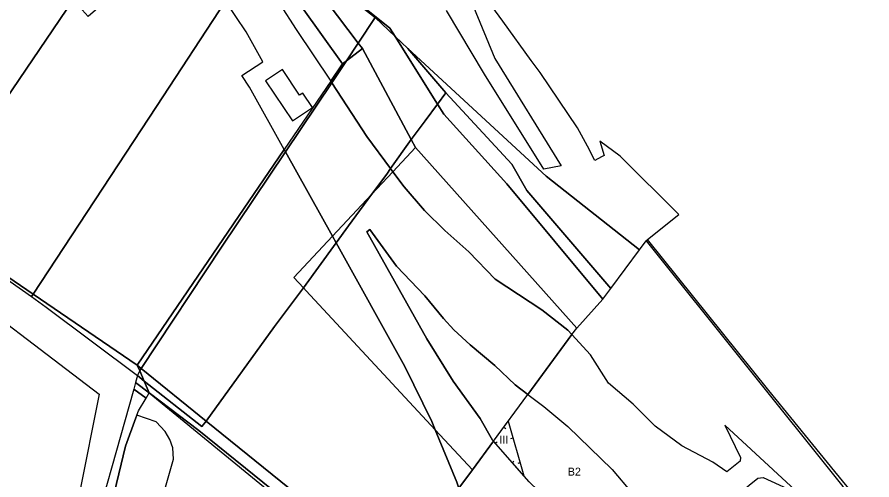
# Model space of a CAD drawing. Extents: x -749314 to -746497, y -1026537 to -1024935.
# Drawn here: x -747475.9 to -747208.9, y -1025525.6 to -1025381 of the extents above; entities that cross this region are included whole.
import ezdxf

# ---------------------------------------------------------------- set-up
doc = ezdxf.new("R2010")
doc.units = 0
for name, color, linetype in [('Default', 7, 'Continuous'), ('K_CD1', 7, 'Continuous'), ('K_JVL', 7, 'Continuous'), ('K_SZDC1', 7, 'Continuous'), ('K_VBP', 7, 'Continuous')]:
    doc.layers.add(name, color=color, linetype=linetype)

msp = doc.modelspace()

# ---------------------------------------------------------------- linework, layer by layer
for points in [[(-747323.86, -1025509.05), (-747323.25, -1025509.5)], [(-747326.54, -1025514.15), (-747325.97, -1025513.66)], [(-747321.03, -1025512.55), (-747321.75, -1025512.75)], [(-747321.28, -1025520.18), (-747320.71, -1025519.68)], [(-747318.83, -1025520.24), (-747319.55, -1025520.45)]]:
    msp.add_lwpolyline(points)
at = {"layer": 'Default'}
for points in [[(-747392.07, -1025423.06), (-747412.02, -1025452.86), (-747437.12, -1025490.76), (-747416.82, -1025507.19), (-747395.49, -1025477.61), (-747386.44, -1025465.56), (-747389.47, -1025462.29), (-747377.41, -1025449.42)], [(-747506.57, -1025443.57), (-747471.41, -1025468.26), (-747470.93, -1025467.52), (-747500.33, -1025447.44), (-747506.13, -1025442.99)], [(-747437.61, -1025491.48), (-747436.18, -1025494.75), (-747418.18, -1025508.87), (-747416.82, -1025507.19), (-747437.12, -1025490.76)]]:
    msp.add_lwpolyline(points, close=True, dxfattribs=at)
msp.add_lwpolyline([(-747316, -1025526.23), (-747327.12, -1025513.48), (-747333.7, -1025522.43), (-747337.88, -1025528.12)], dxfattribs=at)
at = {"layer": 'K_CD1'}
for points in [[(-747352.77, -1025419.24), (-747368.06, -1025390.77), (-747373.01, -1025394.6), (-747377.63, -1025401.49), (-747366.72, -1025418.25), (-747359.26, -1025428.31)], [(-747359.26, -1025428.31), (-747366.72, -1025418.25), (-747377.63, -1025401.49), (-747392.07, -1025423.06), (-747377.41, -1025449.42), (-747365.16, -1025436.35), (-747360.47, -1025430)], [(-747208.9, -1025537.01), (-747220.47, -1025522.93), (-747241.05, -1025497.59), (-747278.95, -1025450.46), (-747279.42, -1025450.84), (-747217.97, -1025527.65)], [(-747438.3, -1025492.99), (-747436.18, -1025494.75), (-747437.61, -1025491.48)], [(-747438.92, -1025495.12), (-747439.45, -1025497.23), (-747435.59, -1025500.01), (-747434.61, -1025498.37)], [(-747361.12, -1025558.08), (-747384.53, -1025538.06), (-747419.14, -1025510.09), (-747434.61, -1025498.37), (-747361.5, -1025558.41)], [(-747284.04, -1025556.36), (-747293.03, -1025547.63), (-747304.14, -1025537.68), (-747316, -1025526.23), (-747327.12, -1025513.48), (-747316.37, -1025498.86), (-747311.37, -1025502.69), (-747303.85, -1025508.85), (-747290.08, -1025522.29), (-747283.88, -1025529.61), (-747275.54, -1025541.17), (-747275.35, -1025542.26), (-747276.77, -1025544.52), (-747277.61, -1025546.19), (-747278.64, -1025548.98), (-747279.07, -1025550.95), (-747279.9, -1025553.1), (-747281.55, -1025559.79)], [(-747442.08, -1025515.07), (-747449.79, -1025546.98), (-747449.22, -1025547.23), (-747433.31, -1025551.36), (-747430.08, -1025539.18), (-747432.54, -1025538.52), (-747427.08, -1025519.14), (-747427.25, -1025515.55), (-747428.21, -1025512.95), (-747429.68, -1025510.41), (-747432.47, -1025507.47), (-747438.47, -1025505.31), (-747438.78, -1025506.15)]]:
    msp.add_lwpolyline(points, close=True, dxfattribs=at)
for points in [[(-747252.17, -1025531.13), (-747244.52, -1025525.04), (-747242.88, -1025524.86), (-747231.5, -1025529.99), (-747254.86, -1025508.52), (-747249.9, -1025518.6), (-747250.01, -1025519.77), (-747254.26, -1025523.08), (-747258.64, -1025520.08), (-747268.31, -1025514.9), (-747276.57, -1025508.79), (-747283.52, -1025501.89), (-747291.18, -1025495.3), (-747296.77, -1025486.54), (-747302.59, -1025480.13), (-747316.37, -1025498.86), (-747311.37, -1025502.69), (-747303.85, -1025508.85), (-747290.08, -1025522.29), (-747283.88, -1025529.61)], [(-747449.79, -1025546.98), (-747442.08, -1025515.07), (-747438.78, -1025506.15), (-747438.47, -1025505.31), (-747437.98, -1025503.99), (-747435.59, -1025500.01), (-747439.45, -1025497.23), (-747454.72, -1025551.44)], [(-747432.54, -1025538.52), (-747427.08, -1025519.14), (-747427.25, -1025515.55), (-747428.21, -1025512.95), (-747429.68, -1025510.41), (-747432.47, -1025507.47), (-747438.47, -1025505.31), (-747437.98, -1025503.99), (-747435.59, -1025500.01), (-747434.61, -1025498.37), (-747361.5, -1025558.41)]]:
    msp.add_lwpolyline(points, dxfattribs=at)
at = {"layer": 'K_JVL'}
msp.add_lwpolyline([(-747544.01, -1025501.28), (-747514.17, -1025471.87), (-747501.71, -1025459.59), (-747450.27, -1025498.83), (-747462.57, -1025560.41), (-747480.42, -1025545.81), (-747535.25, -1025507.41)], close=True, dxfattribs=at)
at = {"layer": 'K_SZDC1'}
for points in [[(-747458.42, -1025375.44), (-747477.66, -1025353.5), (-747478.75, -1025354.46), (-747490.64, -1025340.75), (-747523.03, -1025387.52), (-747481.31, -1025405.83), (-747481.04, -1025405.95), (-747479.48, -1025406.63)], [(-747436.87, -1025341.99), (-747449.37, -1025362.04), (-747441.93, -1025370.6), (-747453.73, -1025380.79), (-747458.42, -1025375.44), (-747479.48, -1025406.63), (-747481.04, -1025405.95), (-747481.31, -1025405.83), (-747506.13, -1025442.99), (-747500.33, -1025447.44), (-747470.93, -1025467.52), (-747432.42, -1025408.86), (-747410.81, -1025375.97), (-747422.12, -1025359.23), (-747433.26, -1025343.94)], [(-747374.23, -1025395.54), (-747373.01, -1025394.6), (-747369.33, -1025389.1), (-747392.02, -1025359.07), (-747397.17, -1025355.01), (-747399.99, -1025359.51)], [(-747357.86, -1025387.05), (-747359.52, -1025384.41), (-747393.71, -1025356.84), (-747392.02, -1025359.07), (-747364.09, -1025381.12)], [(-747401.91, -1025362.44), (-747393.87, -1025376.92), (-747388.71, -1025384.88), (-747377.95, -1025401.01), (-747374.23, -1025395.54), (-747399.99, -1025359.51)], [(-747369.33, -1025389.1), (-747364.09, -1025381.12), (-747392.02, -1025359.07)], [(-747410.81, -1025375.97), (-747401.91, -1025362.44), (-747393.87, -1025376.92), (-747388.71, -1025384.88), (-747377.95, -1025401.01), (-747392.47, -1025422.34), (-747403.31, -1025402.85), (-747405.67, -1025399.16), (-747399.11, -1025394.96), (-747404.32, -1025385.58)], [(-747405.67, -1025399.16), (-747399.11, -1025394.96), (-747404.32, -1025385.58), (-747410.81, -1025375.97), (-747432.42, -1025408.86), (-747470.93, -1025467.52), (-747438.36, -1025489.76), (-747392.47, -1025422.34), (-747403.31, -1025402.85)], [(-747352.77, -1025419.24), (-747348.4, -1025413.39), (-747344.59, -1025408.12), (-747357.86, -1025387.05), (-747364.09, -1025381.12), (-747369.33, -1025389.1), (-747368.06, -1025390.77)], [(-747344.59, -1025408.12), (-747341.95, -1025404.6), (-747353.91, -1025390.81), (-747357.86, -1025387.05)], [(-747373.01, -1025394.6), (-747368.06, -1025390.77), (-747369.33, -1025389.1)], [(-747281.52, -1025453.67), (-747310.6, -1025430.67), (-747353.91, -1025390.81), (-747341.95, -1025404.6), (-747321.38, -1025426.93), (-747316.65, -1025435.15), (-747290.46, -1025465.73)], [(-747373.01, -1025394.6), (-747374.23, -1025395.54), (-747377.95, -1025401.01), (-747392.47, -1025422.34), (-747392.07, -1025423.06), (-747377.63, -1025401.49)], [(-747392.97, -1025397.37), (-747398.27, -1025400.87), (-747389.9, -1025413.36), (-747383.62, -1025409.23), (-747386.68, -1025404.73), (-747387.66, -1025405.38)], [(-747392.97, -1025397.37), (-747398.27, -1025400.87), (-747389.9, -1025413.36), (-747383.62, -1025409.23), (-747386.68, -1025404.73), (-747387.66, -1025405.38)], [(-747321.38, -1025426.93), (-747341.95, -1025404.6), (-747344.59, -1025408.12), (-747342.57, -1025411.33), (-747322.97, -1025433.05), (-747292.93, -1025469.06), (-747290.46, -1025465.73), (-747316.65, -1025435.15)], [(-747301.11, -1025478.12), (-747292.93, -1025469.06), (-747322.97, -1025433.05), (-747342.57, -1025411.33), (-747344.59, -1025408.12), (-747348.4, -1025413.39), (-747352.77, -1025419.24), (-747351.44, -1025421.71)], [(-747359.26, -1025428.31), (-747358.54, -1025429.28), (-747351.44, -1025421.71), (-747352.77, -1025419.24)], [(-747392.47, -1025422.34), (-747438.36, -1025489.76), (-747437.12, -1025490.76), (-747412.02, -1025452.86), (-747392.07, -1025423.06)], [(-747301.11, -1025478.12), (-747351.44, -1025421.71), (-747358.54, -1025429.28), (-747355.05, -1025433.99), (-747348.65, -1025441.35), (-747342.32, -1025447.63), (-747334.77, -1025454.29), (-747326.54, -1025462.8), (-747312.02, -1025472.47), (-747303.85, -1025478.74), (-747302.59, -1025480.13)], [(-747360.47, -1025430), (-747365.16, -1025436.35), (-747358.54, -1025429.28), (-747359.26, -1025428.31)], [(-747342.32, -1025447.63), (-747348.65, -1025441.35), (-747355.05, -1025433.99), (-747358.54, -1025429.28), (-747365.16, -1025436.35), (-747372.44, -1025446.22), (-747376.26, -1025451.49), (-747354.77, -1025490.12), (-747346.39, -1025507.32), (-747345.33, -1025509.89), (-747333.7, -1025522.43), (-747327.12, -1025513.48), (-747327.43, -1025513.12), (-747331.24, -1025506.42), (-747339.72, -1025494.77), (-747347.97, -1025481.48), (-747366.69, -1025448.04), (-747365.7, -1025447.38), (-747357.36, -1025458.77), (-747348.51, -1025468.06), (-747342.76, -1025475.09), (-747339.45, -1025478.66), (-747334.35, -1025483.39), (-747326.72, -1025489.82), (-747320.32, -1025495.83), (-747316.37, -1025498.86), (-747302.59, -1025480.13), (-747303.85, -1025478.74), (-747312.02, -1025472.47), (-747326.54, -1025462.8), (-747334.77, -1025454.29)], [(-747377.41, -1025449.42), (-747376.26, -1025451.49), (-747372.44, -1025446.22), (-747365.16, -1025436.35)], [(-747377.41, -1025449.42), (-747389.47, -1025462.29), (-747386.44, -1025465.56), (-747376.26, -1025451.49)], [(-747327.12, -1025513.48), (-747316.37, -1025498.86), (-747320.32, -1025495.83), (-747326.72, -1025489.82), (-747334.35, -1025483.39), (-747339.45, -1025478.66), (-747342.76, -1025475.09), (-747348.51, -1025468.06), (-747357.36, -1025458.77), (-747365.7, -1025447.38), (-747366.69, -1025448.04), (-747347.97, -1025481.48), (-747339.72, -1025494.77), (-747331.24, -1025506.42), (-747327.43, -1025513.12)], [(-747376.26, -1025451.49), (-747386.44, -1025465.56), (-747385.57, -1025466.49), (-747345.33, -1025509.89), (-747346.39, -1025507.32), (-747354.77, -1025490.12)], [(-747345.33, -1025509.89), (-747385.57, -1025466.49), (-747386.44, -1025465.56), (-747395.49, -1025477.61), (-747416.82, -1025507.19), (-747357.69, -1025555.06), (-747337.88, -1025528.12), (-747338.55, -1025526.3)], [(-747471.41, -1025468.26), (-747466.8, -1025471.61), (-747438.3, -1025492.99), (-747437.61, -1025491.48), (-747438.36, -1025489.76), (-747470.93, -1025467.52)], [(-747438.36, -1025489.76), (-747437.61, -1025491.48), (-747437.12, -1025490.76)], [(-747438.3, -1025492.99), (-747438.92, -1025495.12), (-747434.61, -1025498.37), (-747436.18, -1025494.75)], [(-747357.69, -1025555.06), (-747416.82, -1025507.19), (-747418.18, -1025508.87), (-747436.18, -1025494.75), (-747434.61, -1025498.37), (-747419.14, -1025510.09), (-747384.53, -1025538.06), (-747361.12, -1025558.08)], [(-747337.88, -1025528.12), (-747333.7, -1025522.43), (-747345.33, -1025509.89), (-747338.55, -1025526.3)]]:
    msp.add_lwpolyline(points, close=True, dxfattribs=at)
for points in [[(-747393.71, -1025356.84), (-747359.52, -1025384.41), (-747357.86, -1025387.05), (-747353.91, -1025390.81), (-747310.6, -1025430.67), (-747281.52, -1025453.67), (-747279.42, -1025450.84), (-747278.95, -1025450.46), (-747269.26, -1025442.66), (-747287.53, -1025424.42), (-747293.91, -1025419.77), (-747292.57, -1025424.21), (-747293.36, -1025424.63), (-747295.41, -1025425.73), (-747297.78, -1025421.32), (-747300.87, -1025415.57), (-747312.54, -1025398.3), (-747315.3, -1025394.48), (-747324.15, -1025382.24), (-747331.04, -1025372.72)], [(-747335.3, -1025372.86), (-747326.65, -1025393.89), (-747306.01, -1025427.4), (-747311.43, -1025428.48), (-747329.89, -1025398.76), (-747341.79, -1025378.94)]]:
    msp.add_lwpolyline(points, dxfattribs=at)
at = {"layer": 'K_VBP'}
msp.add_lwpolyline([(-747327.12, -1025513.48), (-747322.54, -1025507.26), (-747317.66, -1025524.32)], close=True, dxfattribs=at)

# ---------------------------------------------------------------- texts
for s, p in [('III', (-747325.24, -1025514.25)), ('B2', (-747303.9, -1025524.25))]:
    msp.add_text(s, height=2.5).set_placement(p)

doc.saveas('drawing.dxf')
